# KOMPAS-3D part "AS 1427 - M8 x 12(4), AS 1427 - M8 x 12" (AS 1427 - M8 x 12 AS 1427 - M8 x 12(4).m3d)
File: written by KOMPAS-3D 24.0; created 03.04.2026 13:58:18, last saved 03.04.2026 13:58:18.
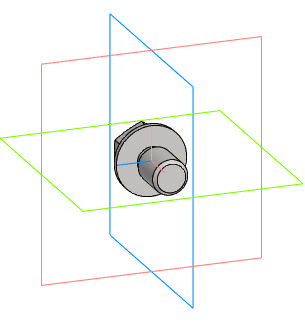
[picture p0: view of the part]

Document properties: Автор: R2D2; Полное имя файла: E:\Работа\Зайцев\Аксессуары для пневмоприводов\Ручной дублер DN.ru\MON2-450-T28-ISO Ручной дублер DN.ru\исходные материалы\AS 1427 - M8 x 12 AS 1427 - M8 x 12(4).m3d

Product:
- Body: Solid1  | qty 1
- Part/product: AS 1427 - M8 x 12(4)  | designation AS 1427 - M8 x 12
    Комментарий: Винты мелкие крепежные   метрические ISO
    additional columns: Сталь, мягкая

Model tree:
1. Solid1  (labels: Solid1)

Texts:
  AS 1427 - M8 x 12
